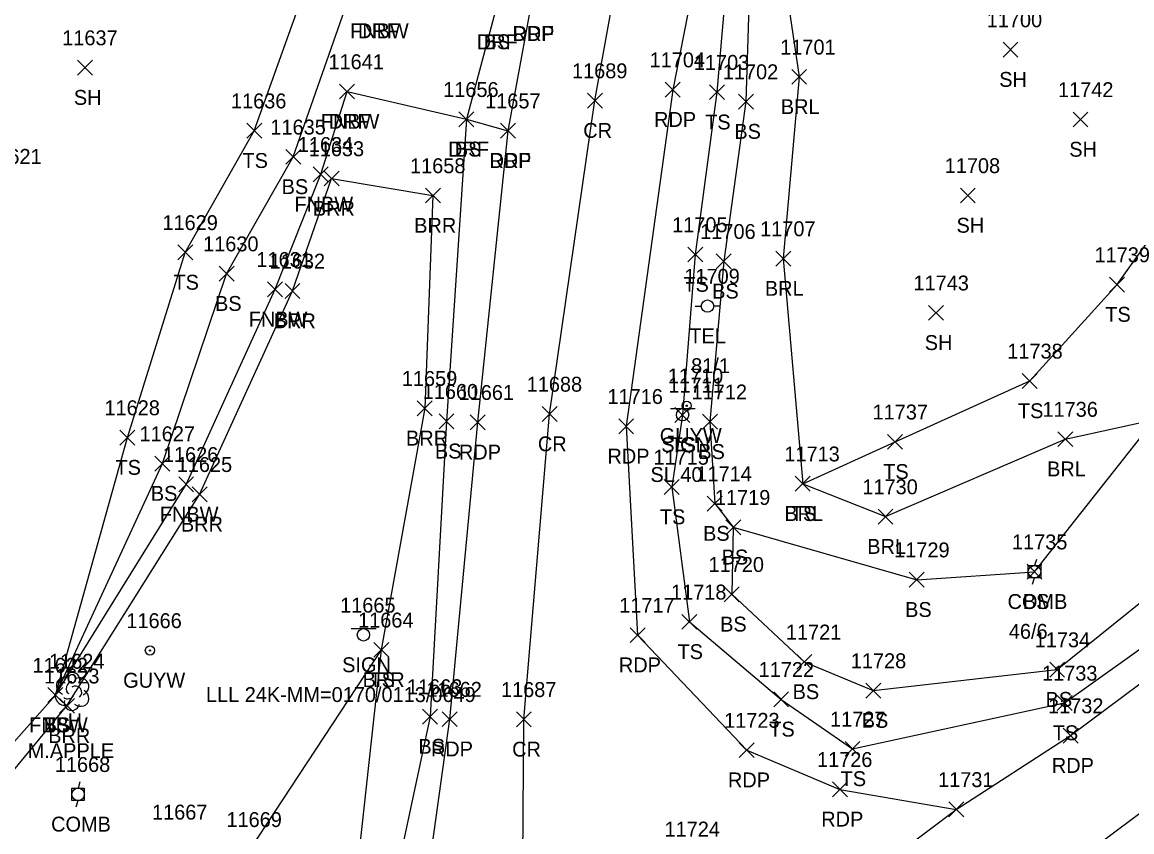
# Model space of a CAD drawing. Extents: x 1475671 to 1477951, y 592661 to 593821.
# Drawn here: x 1476967.1 to 1477116, y 593555 to 593663.7 of the extents above; entities that cross this region are included whole.
import ezdxf

# ---------------------------------------------------------------- set-up
doc = ezdxf.new("R2010")
doc.units = 0
for name, color, linetype in [('L_A', 7, 'Continuous'), ('L_C', 7, 'Continuous'), ('L_I', 7, 'Continuous'), ('L_TIC', 7, 'Continuous'), ('LABL', 7, 'Continuous'), ('LELB', 7, 'Continuous'), ('LFNC', 7, 'Continuous'), ('LTD', 7, 'Continuous'), ('P_A', 7, 'Continuous'), ('P_I', 7, 'Continuous'), ('P_TIC', 7, 'Continuous'), ('PET', 7, 'Continuous'), ('PRC', 7, 'Continuous'), ('R_A', 7, 'Continuous'), ('R_I', 7, 'Continuous'), ('R_TIC', 7, 'Continuous'), ('RDF', 7, 'Continuous'), ('S_A', 7, 'Continuous'), ('S_C', 7, 'Continuous'), ('S_I', 7, 'Continuous'), ('SSGN', 7, 'Continuous'), ('U_A', 7, 'Continuous'), ('U_C', 7, 'Continuous'), ('U_I', 7, 'Continuous'), ('UP', 7, 'Continuous'), ('UPGW', 7, 'Continuous')]:
    doc.layers.add(name, color=color, linetype=linetype)

msp = doc.modelspace()

# ---------------------------------------------------------------- linework, layer by layer
at = {"layer": 'L_TIC'}
for points in [[(1477098.75, 593659.05), (1477100.75, 593661.05)], [(1477100.75, 593659.05), (1477098.75, 593661.05)], [(1476974.55, 593656.63), (1476976.55, 593658.63)], [(1476976.55, 593656.63), (1476974.55, 593658.63)], [(1477070.39, 593655.39), (1477072.39, 593657.39)], [(1477072.39, 593655.39), (1477070.39, 593657.39)], [(1477009.71, 593653.42), (1477011.71, 593655.42)], [(1477011.71, 593653.42), (1477009.71, 593655.42)], [(1477059.36, 593653.33), (1477061.36, 593655.33)], [(1477061.36, 593653.33), (1477059.36, 593655.33)], [(1477063.24, 593652.07), (1477065.24, 593654.07)], [(1477065.24, 593652.07), (1477063.24, 593654.07)], [(1477025.73, 593649.69), (1477027.73, 593651.69)], [(1477027.73, 593649.69), (1477025.73, 593651.69)], [(1477108.15, 593649.67), (1477110.15, 593651.67)], [(1477110.15, 593649.67), (1477108.15, 593651.67)], [(1476997.26, 593648.16), (1476999.26, 593650.16)], [(1476999.26, 593648.16), (1476997.26, 593650.16)], [(1477002.49, 593644.65), (1477004.49, 593646.65)], [(1477004.49, 593644.65), (1477002.49, 593646.65)], [(1477006.17, 593642.31), (1477008.17, 593644.31)], [(1477008.17, 593642.31), (1477006.17, 593644.31)], [(1477007.63, 593641.74), (1477009.63, 593643.74)], [(1477009.63, 593641.74), (1477007.63, 593643.74)], [(1477021.23, 593639.46), (1477023.23, 593641.46)], [(1477023.23, 593639.46), (1477021.23, 593641.46)], [(1477093.02, 593639.47), (1477095.02, 593641.47)], [(1477095.02, 593639.47), (1477093.02, 593641.47)], [(1476988, 593631.82), (1476990, 593633.82)], [(1476990, 593631.82), (1476988, 593633.82)], [(1477056.44, 593631.54), (1477058.44, 593633.54)], [(1477058.44, 593631.54), (1477056.44, 593633.54)], [(1477060.27, 593630.63), (1477062.27, 593632.63)], [(1477062.27, 593630.63), (1477060.27, 593632.63)], [(1477068.25, 593631), (1477070.25, 593633)], [(1477070.25, 593631), (1477068.25, 593633)], [(1476993.55, 593628.97), (1476995.55, 593630.97)], [(1476995.55, 593628.97), (1476993.55, 593630.97)], [(1477000.04, 593626.87), (1477002.04, 593628.87)], [(1477002.04, 593626.87), (1477000.04, 593628.87)], [(1477002.39, 593626.65), (1477004.39, 593628.65)], [(1477004.39, 593626.65), (1477002.39, 593628.65)], [(1477113.06, 593627.51), (1477115.06, 593629.51)], [(1477115.06, 593627.51), (1477113.06, 593629.51)], [(1477088.75, 593623.72), (1477090.75, 593625.72)], [(1477090.75, 593623.72), (1477088.75, 593625.72)], [(1477101.34, 593614.57), (1477103.34, 593616.57)], [(1477103.34, 593614.57), (1477101.34, 593616.57)], [(1477020.13, 593610.9), (1477022.13, 593612.9)], [(1477022.13, 593610.9), (1477020.13, 593612.9)], [(1477054.72, 593610.01), (1477056.72, 593612.01)], [(1477056.72, 593610.01), (1477054.72, 593612.01)], [(1477023.06, 593609.16), (1477025.06, 593611.16)], [(1477025.06, 593609.16), (1477023.06, 593611.16)], [(1477058.41, 593609.09), (1477060.41, 593611.09)], [(1477060.41, 593609.09), (1477058.41, 593611.09)], [(1476980.22, 593606.97), (1476982.22, 593608.97)], [(1476982.22, 593606.97), (1476980.22, 593608.97)], [(1477106.11, 593606.76), (1477108.11, 593608.76)], [(1477108.11, 593606.76), (1477106.11, 593608.76)], [(1477083.26, 593606.4), (1477085.26, 593608.4)], [(1477085.26, 593606.4), (1477083.26, 593608.4)], [(1476984.93, 593603.48), (1476986.93, 593605.48)], [(1476986.93, 593603.48), (1476984.93, 593605.48)], [(1477070.86, 593600.77), (1477072.86, 593602.77)], [(1477072.86, 593600.77), (1477070.86, 593602.77)], [(1477070.86, 593600.77), (1477072.86, 593602.77)], [(1477072.86, 593600.77), (1477070.86, 593602.77)], [(1476988.11, 593600.69), (1476990.11, 593602.69)], [(1476990.11, 593600.69), (1476988.11, 593602.69)], [(1476989.92, 593599.35), (1476991.92, 593601.35)], [(1476991.92, 593599.35), (1476989.92, 593601.35)], [(1477053.29, 593600.33), (1477055.29, 593602.33)], [(1477055.29, 593600.33), (1477053.29, 593602.33)], [(1477059.05, 593598.11), (1477061.05, 593600.11)], [(1477061.05, 593598.11), (1477059.05, 593600.11)], [(1477081.98, 593596.36), (1477083.98, 593598.36)], [(1477083.98, 593596.36), (1477081.98, 593598.36)], [(1477061.54, 593594.93), (1477063.54, 593596.93)], [(1477063.54, 593594.93), (1477061.54, 593596.93)], [(1477061.54, 593594.93), (1477063.54, 593596.93)], [(1477063.54, 593594.93), (1477061.54, 593596.93)], [(1477101.97, 593588.96), (1477103.97, 593590.96)], [(1477103.97, 593588.96), (1477101.97, 593590.96)], [(1477086.17, 593587.89), (1477088.17, 593589.89)], [(1477088.17, 593587.89), (1477086.17, 593589.89)], [(1477061.34, 593585.93), (1477063.34, 593587.93)], [(1477063.34, 593585.93), (1477061.34, 593587.93)], [(1477055.65, 593582.23), (1477057.65, 593584.23)], [(1477057.65, 593582.23), (1477055.65, 593584.23)], [(1477014.31, 593578.47), (1477016.31, 593580.47)], [(1477016.31, 593578.47), (1477014.31, 593580.47)], [(1477014.31, 593578.47), (1477016.31, 593580.47)], [(1477016.31, 593578.47), (1477014.31, 593580.47)], [(1477071.07, 593576.86), (1477073.07, 593578.86)], [(1477073.07, 593576.86), (1477071.07, 593578.86)], [(1477105.02, 593575.82), (1477107.02, 593577.82)], [(1477107.02, 593575.82), (1477105.02, 593577.82)], [(1477080.34, 593573.01), (1477082.34, 593575.01)], [(1477082.34, 593573.01), (1477080.34, 593575.01)], [(1476970.56, 593572.4), (1476972.56, 593574.4)], [(1476972.56, 593572.4), (1476970.56, 593574.4)], [(1476970.56, 593572.4), (1476972.56, 593574.4)], [(1476972.56, 593572.4), (1476970.56, 593574.4)], [(1476970.56, 593572.4), (1476972.56, 593574.4)], [(1476972.56, 593572.4), (1476970.56, 593574.4)], [(1476972.11, 593570.96), (1476974.11, 593572.96)], [(1476974.11, 593570.96), (1476972.11, 593572.96)], [(1477067.97, 593571.83), (1477069.97, 593573.83)], [(1477069.97, 593571.83), (1477067.97, 593573.83)], [(1477106.01, 593571.34), (1477108.01, 593573.34)], [(1477108.01, 593571.34), (1477106.01, 593573.34)], [(1477020.85, 593569.52), (1477022.85, 593571.52)], [(1477022.85, 593569.52), (1477020.85, 593571.52)], [(1477077.55, 593565.18), (1477079.55, 593567.18)], [(1477079.55, 593565.18), (1477077.55, 593567.18)]]:
    msp.add_lwpolyline(points, dxfattribs=at)
at = {"layer": 'LABL'}
for points in [[(1477070.39, 593692.41), (1477067.99, 593679.34), (1477071.39, 593656.39), (1477069.25, 593632), (1477071.86, 593601.77), (1477082.98, 593597.36), (1477107.11, 593607.76), (1477119.12, 593610.41), (1477150.77, 593620.61), (1477191.19, 593657.06), (1477226.2, 593667.71), (1477230.98, 593680.18), (1477228.88, 593689.92), (1477268.63, 593704.57), (1477322.35, 593715.8), (1477370.03, 593723.46), (1477400.06, 593728.47)], [(1476911.91, 593510.8), (1476912.49, 593516.79), (1476929.85, 593528.26), (1476933.94, 593533.82), (1476958.76, 593554.62), (1476973.11, 593571.96), (1476990.92, 593600.35), (1477003.39, 593627.65), (1477008.63, 593642.74), (1477022.23, 593640.46), (1477021.13, 593611.9), (1477015.31, 593579.47), (1476997.65, 593552.69), (1476988.84, 593521.8), (1476973.55, 593506.4)]]:
    msp.add_lwpolyline(points, dxfattribs=at)
at = {"layer": 'LELB'}
for points in [[(1477064.35, 593692.56), (1477062.58, 593680.23), (1477060.36, 593654.33), (1477057.44, 593632.54), (1477055.72, 593611.01), (1477054.29, 593601.33), (1477056.65, 593583.23), (1477068.97, 593572.83), (1477078.55, 593566.18), (1477107.01, 593572.34), (1477124.47, 593584.78), (1477157.24, 593607.25), (1477189.46, 593630.34), (1477226.15, 593653.98), (1477273.87, 593682.48), (1477330.28, 593697.97), (1477374.36, 593710.64), (1477415.47, 593719.43), (1477468.07, 593729.59), (1477496.83, 593733.35), (1477522.49, 593736.3), (1477565.44, 593741.31)], [(1477062.54, 593595.93), (1477087.17, 593588.89), (1477102.97, 593589.96), (1477119.12, 593610.41), (1477134.07, 593632.51), (1477152.16, 593650.25), (1477153.66, 593657.12), (1477163.06, 593661.03), (1477185.94, 593664.32), (1477226.2, 593667.71), (1477271.58, 593688.8), (1477328.93, 593700.99), (1477373.48, 593714.07)], [(1476971.56, 593573.4), (1476981.22, 593607.97), (1476989, 593632.82), (1476998.26, 593649.16), (1477006.68, 593672.75), (1477020.69, 593684.42), (1477026.64, 593692.51), (1477028.82, 593699.64)], [(1476971.56, 593573.4), (1476985.93, 593604.48), (1476994.55, 593629.97), (1477003.49, 593645.65), (1477011.62, 593668.92), (1477016.36, 593671.4), (1477028.62, 593686.72), (1477037.33, 593699.08), (1477030.58, 593665.1), (1477026.73, 593650.69), (1477024.06, 593610.16), (1477021.85, 593570.52), (1477015.22, 593539.33), (1477014.29, 593516.42)], [(1477066.48, 593692), (1477065.09, 593680.02), (1477064.24, 593653.07), (1477061.27, 593631.63), (1477059.41, 593610.09), (1477060.05, 593599.11), (1477062.54, 593595.93), (1477062.34, 593586.93), (1477072.07, 593577.86), (1477081.34, 593574.01), (1477106.02, 593576.82), (1477123.2, 593590.66), (1477155.04, 593611.76), (1477188.09, 593633.22), (1477228.3, 593659.4)], [(1477071.86, 593601.77), (1477084.26, 593607.4), (1477102.34, 593615.57), (1477114.06, 593628.51), (1477125.22, 593644.08), (1477133.19, 593668.55)], [(1477015.31, 593579.47), (1477011.01, 593540.24), (1477007.01, 593515.21), (1476993.8, 593498.58)]]:
    msp.add_lwpolyline(points, dxfattribs=at)
at = {"layer": 'LFNC'}
msp.add_lwpolyline([(1476903.53, 593512.02), (1476906.35, 593515.38), (1476915.35, 593522.29), (1476924.14, 593529.67), (1476933.23, 593536.43), (1476956.51, 593556.41), (1476971.56, 593573.4), (1476989.11, 593601.69), (1477001.04, 593627.87), (1477007.17, 593643.31), (1477010.71, 593654.42)], dxfattribs=at)
at = {"layer": 'LTD'}
msp.add_line((1476973.78, 593573.94), (1476973.78, 593573.94), dxfattribs=at)
msp.add_line((1476973.78, 593573.94), (1476973.78, 593573.94), dxfattribs=at)
msp.add_arc((1476973.83, 593575.38), 1.05, 335.5272, 180.9563, dxfattribs=at)
for centre, major_axis, ratio, start_param, end_param in [((1476972.99, 593574.61), (1.21, -0.51), 0.895232, 1.570796, 4.712389), ((1476973.57, 593574.4), (-0.208, -0.792), 0.645439, 3.141593, 6.283185), ((1476974.28, 593573.78), (-0.5, 0.667), 0.989748, 3.141593, 6.283185), ((1476974.82, 593574.53), (-1.14, -0.48), 0.949671, 1.570796, 4.712389), ((1476972.7, 593573.23), (0.58, -1.04), 0.959034, 3.141593, 6.283185), ((1476973.32, 593573.19), (-0.625, -0.083), 0.423636, 0, 3.141593), ((1476974.78, 593573.11), (-1.09, 0.79), 0.841452, 1.570796, 4.712389), ((1476973.78, 593572.44), (0.26, 1.06), 0.942809, 1.570796, 4.712389)]:
    msp.add_ellipse(centre, major_axis=major_axis, ratio=ratio, start_param=start_param, end_param=end_param, dxfattribs=at)
at = {"layer": 'P_TIC'}
for points in [[(1477053.42, 593653.67), (1477055.42, 593655.67)], [(1477055.42, 593653.67), (1477053.42, 593655.67)], [(1477042.98, 593652.2), (1477044.98, 593654.2)], [(1477044.98, 593652.2), (1477042.98, 593654.2)], [(1477031.31, 593648.16), (1477033.31, 593650.16)], [(1477033.31, 593648.16), (1477031.31, 593650.16)], [(1477036.89, 593610.13), (1477038.89, 593612.13)], [(1477038.89, 593610.13), (1477036.89, 593612.13)], [(1477027.23, 593609.02), (1477029.23, 593611.02)], [(1477029.23, 593609.02), (1477027.23, 593611.02)], [(1477047.17, 593608.48), (1477049.17, 593610.48)], [(1477049.17, 593608.48), (1477047.17, 593610.48)], [(1477048.7, 593580.45), (1477050.7, 593582.45)], [(1477050.7, 593580.45), (1477048.7, 593582.45)], [(1477023.47, 593569.17), (1477025.47, 593571.17)], [(1477025.47, 593569.17), (1477023.47, 593571.17)], [(1477033.44, 593569.14), (1477035.44, 593571.14)], [(1477035.44, 593569.14), (1477033.44, 593571.14)], [(1477106.82, 593566.96), (1477108.82, 593568.96)], [(1477108.82, 593566.96), (1477106.82, 593568.96)], [(1477063.35, 593565.01), (1477065.35, 593567.01)], [(1477065.35, 593565.01), (1477063.35, 593567.01)], [(1477075.86, 593559.75), (1477077.86, 593561.75)], [(1477077.86, 593559.75), (1477075.86, 593561.75)], [(1477091.48, 593557.05), (1477093.48, 593559.05)], [(1477093.48, 593557.05), (1477091.48, 593559.05)], [(1477091.48, 593557.05), (1477093.48, 593559.05)], [(1477093.48, 593557.05), (1477091.48, 593559.05)]]:
    msp.add_lwpolyline(points, dxfattribs=at)
at = {"layer": 'PET'}
for points in [[(1476922.98, 593419.08), (1476952.36, 593443.37), (1476980.99, 593467.2), (1477001.29, 593483.18), (1477023.09, 593498.99), (1477048.41, 593522.27), (1477069.64, 593540.85), (1477092.48, 593558.05), (1477107.82, 593567.96), (1477124.14, 593580.14), (1477159.25, 593604.27), (1477192.28, 593625.33), (1477229.26, 593646.84), (1477278.16, 593671.86), (1477332.19, 593694.33), (1477375.16, 593706.96), (1477415.75, 593716.85), (1477468.99, 593725.32)], [(1477040.93, 593697.02), (1477035.4, 593666.2), (1477032.31, 593649.16), (1477028.23, 593610.02), (1477024.47, 593570.17), (1477019.98, 593537.99), (1477014.29, 593516.42), (1477009.62, 593503.76), (1477001.29, 593483.18)], [(1477061.93, 593692.95), (1477054.42, 593654.67), (1477048.17, 593609.48), (1477049.7, 593581.45), (1477064.35, 593566.01), (1477076.86, 593560.75), (1477092.48, 593558.05)]]:
    msp.add_lwpolyline(points, dxfattribs=at)
at = {"layer": 'PRC'}
for points in [[(1476934.06, 593407.68), (1476963.46, 593432.81), (1476989.48, 593455.26), (1477029.64, 593488.99), (1477062.06, 593515.29), (1477088.32, 593536.02), (1477123.8, 593562.56), (1477162.82, 593589.95), (1477199.33, 593613.78), (1477232.88, 593633.31), (1477283.55, 593659.16), (1477336.93, 593680.98), (1477378.09, 593693.68), (1477418.39, 593702.94), (1477470.82, 593711.77)], [(1477048.41, 593522.27), (1477034.19, 593538.42), (1477034.44, 593570.14), (1477037.89, 593611.13), (1477043.98, 593653.2), (1477051.59, 593695.26)]]:
    msp.add_lwpolyline(points, dxfattribs=at)
at = {"layer": 'R_TIC'}
for points in [[(1477009.71, 593653.42), (1477011.71, 593655.42)], [(1477011.71, 593653.42), (1477009.71, 593655.42)], [(1477025.73, 593649.69), (1477027.73, 593651.69)], [(1477027.73, 593649.69), (1477025.73, 593651.69)], [(1477031.31, 593648.16), (1477033.31, 593650.16)], [(1477033.31, 593648.16), (1477031.31, 593650.16)]]:
    msp.add_lwpolyline(points, dxfattribs=at)
at = {"layer": 'RDF'}
msp.add_lwpolyline([(1477010.71, 593654.42), (1477026.73, 593650.69), (1477032.31, 593649.16)], dxfattribs=at)
at = {"layer": 'SSGN'}
for p, q in [((1477054.1, 593611.86), (1477057.43, 593611.86)), ((1477055.74, 593611.03), (1477055.74, 593611.03)), ((1477011.27, 593582.32), (1477014.6, 593582.32)), ((1477012.91, 593581.49), (1477012.91, 593581.49))]:
    msp.add_line(p, q, dxfattribs=at)
for centre in [(1477055.74, 593611.03), (1477012.91, 593581.49)]:
    msp.add_circle(centre, 0.833, dxfattribs=at)
at = {"layer": 'UP'}
for p, q in [((1477057.44, 593625.62), (1477058.26, 593625.62)), ((1477059.09, 593625.62), (1477059.09, 593625.62)), ((1477060.76, 593625.62), (1477059.93, 593625.62)), ((1477059.93, 593625.62), (1477059.93, 593625.62)), ((1477060.76, 593625.62), (1477060.76, 593625.62)), ((1477103.22, 593591.62), (1477102.97, 593590.79)), ((1477102.14, 593589.12), (1477102.14, 593590.79)), ((1477102.14, 593590.79), (1477103.81, 593590.79)), ((1477102.97, 593589.96), (1477102.97, 593589.96)), ((1477103.81, 593590.79), (1477103.81, 593589.12)), ((1477103.81, 593589.12), (1477102.14, 593589.12)), ((1477102.72, 593588.29), (1477102.97, 593589.12)), ((1476974.86, 593561.74), (1476974.61, 593560.91)), ((1476973.77, 593559.24), (1476973.77, 593560.91)), ((1476973.77, 593560.91), (1476975.44, 593560.91)), ((1476974.61, 593560.08), (1476974.61, 593560.08)), ((1476975.44, 593560.91), (1476975.44, 593559.24)), ((1476975.44, 593559.24), (1476973.77, 593559.24)), ((1476974.36, 593558.41), (1476974.61, 593559.24))]:
    msp.add_line(p, q, dxfattribs=at)
for centre in [(1477059.09, 593625.62), (1477102.97, 593589.96), (1476974.61, 593560.08)]:
    msp.add_circle(centre, 0.833, dxfattribs=at)
at = {"layer": 'UPGW'}
for centre, radius in [((1477056.29, 593612.24), 0.625), ((1477056.29, 593612.24), 0.0833), ((1476984.26, 593579.39), 0.625), ((1476984.26, 593579.39), 0.0833)]:
    msp.add_circle(centre, radius, dxfattribs=at)

# ---------------------------------------------------------------- texts
at = {"layer": 'L_A'}
for s, p in [('FNBW', (1477011.11, 593661.57)), ('BS', (1477029.03, 593660.1)), ('SH', (1477098.24, 593655.05)), ('SH', (1476974.04, 593652.63)), ('BRL', (1477068.93, 593651.39)), ('FNBW', (1477007.18, 593649.42)), ('TS', (1477058.77, 593649.33)), ('BS', (1477062.69, 593648.07)), ('BS', (1477025.17, 593645.69)), ('SH', (1477107.64, 593645.67)), ('TS', (1476996.67, 593644.16)), ('BS', (1477001.93, 593640.65)), ('FNBW', (1477003.65, 593638.31)), ('BRR', (1477006.12, 593637.74)), ('BRR', (1477019.72, 593635.46)), ('SH', (1477092.51, 593635.47)), ('TS', (1476987.41, 593627.82)), ('TS', (1477055.85, 593627.54)), ('BS', (1477059.71, 593626.63)), ('BRL', (1477066.79, 593627)), ('BS', (1476992.99, 593624.97)), ('TS', (1477112.47, 593623.51)), ('FNBW', (1476997.51, 593622.87)), ('BRR', (1477000.87, 593622.65)), ('SH', (1477088.24, 593619.72)), ('TS', (1477100.75, 593610.57)), ('BRR', (1477018.62, 593606.9)), ('BS', (1477022.5, 593605.16)), ('TS', (1477054.13, 593606.01)), ('BS', (1477057.85, 593605.09)), ('TS', (1476979.63, 593602.97)), ('TS', (1477082.67, 593602.4)), ('BRL', (1477104.66, 593602.76)), ('BS', (1476984.37, 593599.48)), ('FNBW', (1476985.58, 593596.69)), ('TS', (1477052.7, 593596.33)), ('BRL', (1477069.4, 593596.77)), ('TS', (1477070.26, 593596.77)), ('BRR', (1476988.41, 593595.35)), ('BS', (1477058.49, 593594.11)), ('BRL', (1477080.53, 593592.36)), ('BS', (1477060.98, 593590.93)), ('BS', (1477060.98, 593590.93)), ('BS', (1477101.41, 593584.96)), ('BS', (1477085.61, 593583.89)), ('BS', (1477060.78, 593581.93)), ('TS', (1477055.06, 593578.23)), ('BRR', (1477012.8, 593574.47)), ('TS', (1477013.72, 593574.47)), ('BS', (1477070.51, 593572.86)), ('BS', (1477104.46, 593571.82)), ('FNBW', (1476968.03, 593568.4)), ('TS', (1476969.97, 593568.4)), ('BS', (1476970, 593568.4)), ('H', (1476973.22, 593568.94)), ('BS', (1477079.78, 593569.01)), ('BRR', (1476970.6, 593566.96)), ('TS', (1477067.38, 593567.83)), ('TS', (1477105.42, 593567.34)), ('BS', (1477020.29, 593565.52)), ('TS', (1477076.96, 593561.18))]:
    msp.add_text(s, height=2, dxfattribs=at).set_placement(p)
at = {"layer": 'L_C'}
msp.add_text('M.APPLE', height=2, dxfattribs=at).set_placement((1476967.85, 593564.94))
at = {"layer": 'L_I'}
for s, p in [('11700', (1477096.56, 593663.05)), ('11637', (1476972.48, 593660.63)), ('11701', (1477068.85, 593659.39)), ('11641', (1477008.21, 593657.42)), ('11703', (1477057.25, 593657.33)), ('11702', (1477061.14, 593656.07)), ('11656', (1477023.61, 593653.69)), ('11742', (1477106.13, 593653.67)), ('11636', (1476995.13, 593652.16)), ('11635', (1477000.42, 593648.65)), ('11634', (1477004.1, 593646.31)), ('11633', (1477005.56, 593645.74)), ('11621', (1476962.28, 593644.71)), ('11658', (1477019.16, 593643.46)), ('11708', (1477090.92, 593643.47)), ('11629', (1476985.93, 593635.82)), ('11705', (1477054.34, 593635.54)), ('11707', (1477066.15, 593635)), ('11706', (1477058.11, 593634.63)), ('11630', (1476991.39, 593632.97)), ('11631', (1476998.54, 593630.87)), ('11632', (1477000.32, 593630.65)), ('11739', (1477111.03, 593631.51)), ('11743', (1477086.73, 593627.72)), ('11738', (1477099.32, 593618.57)), ('11659', (1477018.06, 593614.9)), ('11660', (1477020.86, 593613.16)), ('11711', (1477053.83, 593614.01)), ('11712', (1477056.95, 593613.09)), ('11628', (1476978.15, 593610.97)), ('11737', (1477081.24, 593610.4)), ('11736', (1477104.04, 593610.76)), ('11627', (1476982.86, 593607.48)), ('11626', (1476985.99, 593604.69)), ('11715', (1477051.83, 593604.33)), ('11713', (1477069.4, 593604.77)), ('11713', (1477069.4, 593604.77)), ('11625', (1476987.85, 593603.35)), ('11714', (1477057.59, 593602.11)), ('11730', (1477079.87, 593600.36)), ('11719', (1477060.08, 593598.93)), ('11719', (1477060.08, 593598.93)), ('11729', (1477084.14, 593591.89)), ('11735', (1477099.95, 593592.96)), ('11720', (1477059.23, 593589.93)), ('11718', (1477054.19, 593586.23)), ('11664', (1477012.19, 593582.47)), ('11664', (1477012.19, 593582.47)), ('11721', (1477069.61, 593580.86)), ('11734', (1477103, 593579.82)), ('11624', (1476970.71, 593576.94)), ('11728', (1477078.32, 593577.01)), ('11622', (1476968.49, 593576.4)), ('11622', (1476968.49, 593576.4)), ('11622', (1476968.49, 593576.4)), ('11722', (1477065.95, 593575.83)), ('11623', (1476970.04, 593574.96)), ('11733', (1477103.98, 593575.34)), ('11663', (1477018.74, 593573.52)), ('11727', (1477075.53, 593569.18)), ('11669', (1476994.52, 593555.69)), ('11724', (1477053.32, 593554.41))]:
    msp.add_text(s, height=2, dxfattribs=at).set_placement(p)
at = {"layer": 'P_A'}
for s, p in [('RDP', (1477032.89, 593661.2)), ('RDP', (1477051.91, 593649.67)), ('CR', (1477042.41, 593648.2)), ('RDP', (1477029.8, 593644.16)), ('CR', (1477036.32, 593606.13)), ('RDP', (1477025.72, 593605.02)), ('RDP', (1477045.66, 593604.48)), ('RDP', (1477047.19, 593576.45)), ('RDP', (1477021.96, 593565.17)), ('CR', (1477032.87, 593565.14)), ('RDP', (1477105.3, 593562.96)), ('RDP', (1477061.83, 593561.01)), ('RDP', (1477074.35, 593555.75))]:
    msp.add_text(s, height=2, dxfattribs=at).set_placement(p)
at = {"layer": 'P_I'}
for s, p in [('11704', (1477051.32, 593657.67)), ('11689', (1477040.9, 593656.2)), ('11657', (1477029.24, 593652.16)), ('11688', (1477034.82, 593614.13)), ('11661', (1477025.68, 593613.02)), ('11716', (1477045.66, 593612.48)), ('11717', (1477047.24, 593584.45)), ('11662', (1477021.36, 593573.17)), ('11687', (1477031.37, 593573.14)), ('11732', (1477104.79, 593570.96)), ('11723', (1477061.32, 593569.01)), ('11726', (1477073.78, 593563.75)), ('11731', (1477090.03, 593561.05)), ('11731', (1477090.03, 593561.05))]:
    msp.add_text(s, height=2, dxfattribs=at).set_placement(p)
at = {"layer": 'R_A'}
for p in [(1477012.17, 593661.57), (1477032.94, 593661.2), (1477028.12, 593660.1), (1477008.25, 593649.42), (1477024.27, 593645.69), (1477029.85, 593644.16)]:
    msp.add_text('DRF', height=2, dxfattribs=at).set_placement(p)
at = {"layer": 'R_I'}
for s, p in [('11641', (1477008.21, 593657.42)), ('11656', (1477023.61, 593653.69)), ('11657', (1477029.24, 593652.16))]:
    msp.add_text(s, height=2, dxfattribs=at).set_placement(p)
at = {"layer": 'S_A'}
for p in [(1477052.88, 593606.01), (1477010.05, 593576.47)]:
    msp.add_text('SIGN', height=2, dxfattribs=at).set_placement(p)
at = {"layer": 'S_C'}
for s, p in [('SL 40', (1477051.43, 593602.01)), ('LLL 24K-MM=0170/0113/0649', (1476991.77, 593572.47))]:
    msp.add_text(s, height=2, dxfattribs=at).set_placement(p)
at = {"layer": 'S_I'}
for s, p in [('11711', (1477053.83, 593614.01)), ('11665', (1477009.78, 593584.47))]:
    msp.add_text(s, height=2, dxfattribs=at).set_placement(p)
at = {"layer": 'U_A'}
for s, p in [('TEL', (1477056.65, 593620.62)), ('GUYW', (1477052.68, 593607.24)), ('COMB', (1477099.36, 593584.96)), ('GUYW', (1476980.66, 593574.39)), ('COMB', (1476970.99, 593555.08))]:
    msp.add_text(s, height=2, dxfattribs=at).set_placement(p)
at = {"layer": 'U_C'}
for s, p in [('81/1', (1477056.89, 593616.62)), ('46/6', (1477099.53, 593580.96))]:
    msp.add_text(s, height=2, dxfattribs=at).set_placement(p)
at = {"layer": 'U_I'}
for s, p in [('11709', (1477055.98, 593628.62)), ('11710', (1477053.75, 593615.24)), ('11735', (1477099.95, 593592.96)), ('11666', (1476981.09, 593582.39)), ('11668', (1476971.49, 593563.08)), ('11667', (1476984.53, 593556.69))]:
    msp.add_text(s, height=2, dxfattribs=at).set_placement(p)

doc.saveas('drawing.dxf')
